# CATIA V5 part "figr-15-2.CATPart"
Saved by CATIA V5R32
Part number: Part1
Bounding box of the stored display mesh (mm): x -101.427 to 121.258, y -118.645 to 66.112, z 0 to 1
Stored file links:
  D:\PROJECTS\Project 2022\CATIA V5 6R 2022\Resources\Part Files\c15_catia_v5_6r2022_prt\figr-15-2.CATPart
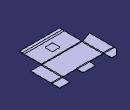
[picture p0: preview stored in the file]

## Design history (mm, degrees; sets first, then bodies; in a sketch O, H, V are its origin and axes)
SheetMetalParameters1: Thickness 1, BendRadius 2, KFactor 0.400515 {= log(min(100,max(20*SheetMetalParameters1.BendRadius,SheetMetalParameters1.Thickness)/SheetMetalParameters1.Thickness))/log(100)/2}, ReliefRadialLength 1, ReliefAxialLength 2, WallPerLength 50, MinimumBendRadius 0
Body1 (main body)
  Sketch1 on xy-plane, origin (0, 0, 0), H (1, 0, 0), V (0, 1, 0)
    line L1 (-62.6567, 37.3409) -> (82.4875, 37.3409)
    line L2 (82.4875, 37.3409) -> (82.4875, -38.1848)
    line L3 (82.4875, -38.1848) -> (-62.6567, -38.1848)
    line L4 (-62.6567, -38.1848) -> (-62.6567, 37.3409)
    horizontal: L1 H, L3 H
    vertical: L2 V, L4 V
  Wall1: Thickness 1, Profile Sketch1, OffsetValue 0
  d_NewWallOnEdge1: NewWallOnEdge_Length 25, NewWallOnEdge_HeightLimitOffset 0, NewWallOnEdge_WidthOffset1 -50, NewWallOnEdge_WidthOffset2 -50, NewWallOnEdge_Angle 90, NewWallOnEdge_BendRadiusValue 2 {= SheetMetalParameters1.BendRadius}, NewWallOnEdge_BendTable SheetMetalParameters1, NewWallOnEdge_Edge edge [face of Wall1 | face of Wall1], NewWallOnEdge_GapValue 0, KFacteur 0.400515 {= log(min(100,max(20*d_NewWallOnEdge1.Radius,SheetMetalParameters1.Thickness)/SheetMetalParameters1.Thickness))/log(100)/2}
  d_NewWallOnEdge2: NewWallOnEdge_Length 40, NewWallOnEdge_HeightLimitOffset 0, NewWallOnEdge_WidthOffset1 0, NewWallOnEdge_WidthOffset2 0, NewWallOnEdge_Angle 90, NewWallOnEdge_BendRadiusValue 2 {= SheetMetalParameters1.BendRadius}, NewWallOnEdge_BendTable SheetMetalParameters1, NewWallOnEdge_Edge edge [face of Wall1 | face of Wall1], NewWallOnEdge_GapValue 0, KFacteur 0.400515 {= log(min(100,max(20*d_NewWallOnEdge2.Radius,SheetMetalParameters1.Thickness)/SheetMetalParameters1.Thickness))/log(100)/2}
  d_NewWallOnEdge3: NewWallOnEdge_Length 30, NewWallOnEdge_HeightLimitOffset 0, NewWallOnEdge_WidthOffset1 0, NewWallOnEdge_WidthOffset2 0, NewWallOnEdge_Angle 90, NewWallOnEdge_BendRadiusValue 2 {= SheetMetalParameters1.BendRadius}, NewWallOnEdge_BendTable SheetMetalParameters1, NewWallOnEdge_Edge edge [face of d_NewWallOnEdge2 | face of d_NewWallOnEdge2], NewWallOnEdge_GapValue 0, KFacteur 0.400515 {= log(min(100,max(20*d_NewWallOnEdge3.Radius,SheetMetalParameters1.Thickness)/SheetMetalParameters1.Thickness))/log(100)/2}
  d_NewWallOnEdge4: NewWallOnEdge_Length 60, NewWallOnEdge_HeightLimitOffset 0, NewWallOnEdge_WidthOffset1 0, NewWallOnEdge_WidthOffset2 0, NewWallOnEdge_Angle 110, NewWallOnEdge_BendRadiusValue 2 {= SheetMetalParameters1.BendRadius}, NewWallOnEdge_BendTable SheetMetalParameters1, NewWallOnEdge_Edge edge [face of Wall1 | face of Wall1], NewWallOnEdge_GapValue 0, KFacteur 0.400515 {= log(min(100,max(20*d_NewWallOnEdge4.Radius,SheetMetalParameters1.Thickness)/SheetMetalParameters1.Thickness))/log(100)/2}
  Flange1: Angle 90, Length 10, Radius 2 {= SheetMetalParameters1.BendRadius}, KFacteur 0.400515 {= log(min(100,max(20*Flange1.Radius,SheetMetalParameters1.Thickness)/SheetMetalParameters1.Thickness))/log(100)/2}, Guide edge [face of d_NewWallOnEdge4 | face of d_NewWallOnEdge4]
  d_NewWallOnEdge5: NewWallOnEdge_Length 40, NewWallOnEdge_HeightLimitOffset 0, NewWallOnEdge_WidthLimit2 face of d_NewWallOnEdge4, NewWallOnEdge_WidthOffset1 0, NewWallOnEdge_WidthOffset2 -2, NewWallOnEdge_Angle 90, NewWallOnEdge_WithBend true, NewWallOnEdge_BendRadiusValue 2 {= SheetMetalParameters1.BendRadius}, NewWallOnEdge_BendTable SheetMetalParameters1, NewWallOnEdge_Edge edge [face of Wall1 | face of Wall1], NewWallOnEdge_GapValue 0, KFacteur 0.400515 {= log(min(100,max(20*d_NewWallOnEdge5.Radius,SheetMetalParameters1.Thickness)/SheetMetalParameters1.Thickness))/log(100)/2}
  d_NewWallOnEdge6: NewWallOnEdge_Length 30, NewWallOnEdge_HeightLimitOffset 0, NewWallOnEdge_WidthOffset1 0, NewWallOnEdge_WidthOffset2 0, NewWallOnEdge_Angle 90, NewWallOnEdge_BendRadiusValue 2 {= SheetMetalParameters1.BendRadius}, NewWallOnEdge_BendTable SheetMetalParameters1, NewWallOnEdge_Edge edge [face of d_NewWallOnEdge5 | face of d_NewWallOnEdge5], NewWallOnEdge_GapValue 0, KFacteur 0.400515 {= log(min(100,max(20*d_NewWallOnEdge6.Radius,SheetMetalParameters1.Thickness)/SheetMetalParameters1.Thickness))/log(100)/2}
  Chamfer1: ChamferAngle 45, ChamferLength1 20, ChamferLength2 0.5, ChamferPropagation 1, ChamferReverse false, ChamferType 1, CornerChamferEdges edge [face of d_NewWallOnEdge6 | face of d_NewWallOnEdge6]
  Corner1: CornerRadius 3, CornerChamferEdges (edge [face of d_NewWallOnEdge1 | face of d_NewWallOnEdge1]; edge [face of d_NewWallOnEdge1 | face of d_NewWallOnEdge1])
  Sketch2 on face of d_NewWallOnEdge4, origin (8.9154, -38.1848, 1), H (1, 0, 0), V (0, -0.342, 0.9397)
    line L1 (-12.2908, 45.4061) -> (12.3784, 45.4061)
    line L2 (12.3784, 45.4061) -> (12.3784, 21.719)
    line L3 (12.3784, 21.719) -> (-12.2908, 21.719)
    line L4 (-12.2908, 21.719) -> (-12.2908, 45.4061)
    horizontal: L1 H, L3 H
    vertical: L2 V, L4 V
  d_Stamp1: NewRoot_AttribNormalisation "No Standard", Stamp_FilletRadius 1, Stamp_IntersectFilletRadius 2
